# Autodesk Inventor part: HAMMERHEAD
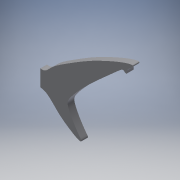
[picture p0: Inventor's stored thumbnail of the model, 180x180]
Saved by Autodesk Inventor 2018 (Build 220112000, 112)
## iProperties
Created: 2019-06
Part Number: HAMMERHEAD
Material: Generic
Document SubType Name: Modeling
Designer: multivac
Density: 1 g/cm^3
Appearance: Default
Author: multivac
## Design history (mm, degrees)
sketch "Sketch1"
  geometry: L1 (-121.659, 50.404)-(56.189, 50.404); L2 (56.189, 50.404)-(56.189, -28.23); L3 (56.189, -28.23)-(-121.659, -28.23); L4 (-121.659, -28.23)-(-121.659, 50.404); L5 (0.653, 15.594)-(3.508, 15.097); L6 (3.508, 15.097)-(6.301, 17.022); L7 (6.301, 17.022)-(9.219, 21.367); L8 (9.219, 21.367)-(18.033, 27.016); L9 (18.033, 27.016)-(25.42, 31.733); L10 (25.42, 31.733)-(37.711, 39.368); L11 (37.711, 39.368)-(50.622, 45.576); L12 (50.622, 45.576)-(62.913, 50.976); L13 (62.913, 50.976)-(70.61, 53.149); L14 (70.61, 53.149)-(71.26, 52.492); L15 (71.26, 52.492)-(71.26, 51.488); L16 (71.26, 51.488)-(66.753, 48.312); L17 (66.753, 48.312)-(66.613, 46.818); L18 (66.613, 46.818)-(66.847, 45.183); L19 (66.847, 45.183)-(66.076, 44.459); L20 (66.076, 44.459)-(64.722, 45.23); L21 (64.722, 45.23)-(63.858, 46.374); L22 (63.858, 46.374)-(62.223, 45.883); L23 (62.223, 45.883)-(53.746, 37.92); L24 (53.746, 37.92)-(35.368, 22.064); L25 (35.368, 22.064)-(23.061, 7.796); L26 (23.061, 7.796)-(20.586, 3.592); L27 (20.586, 3.592)-(22.36, -0.495); L28 (22.36, -0.495)-(24.999, -6.473); L29 (24.999, -6.473)-(30.417, -14.459); L30 (30.417, -14.459)-(32.379, -16.444); L31 (32.379, -16.444)-(31.748, -17.705); L32 (31.748, -17.705)-(28.409, -16.865); L33 (28.409, -16.865)-(19.161, -10.793); L34 (19.161, -10.793)-(14.701, -7.524); L35 (14.701, -7.524)-(8.396, -0.495); L36 (8.396, -0.495)-(4.402, 2.775); L37 (4.402, 2.775)-(0.653, 3.09); L38 (0.653, 15.594)-(0.653, 3.09); 1 other entity
  constraints: 2 end point, 2 vertical, 5 other
extrude "Extrusion1" new body sketch "Sketch1" distance "d16" = 5; taper "d17" = 0 deg
sketch "Sketch2"
  geometry: L1 (-0.653, 0)-(-0.653, 5) reference; L2 (-0.653, 5)-(-74.207, 2.5); L3 (-74.207, 2.5)-(-0.653, 0); L4 (-0.653, 0)-(-0.653, 5); 1 further point
  constraints: 6 end point, 1 collinear
extrude "Extrusion2" sketch "Sketch2" distance "d26" = 60; taper "d28" = 0 deg; dims "d27" = 25, "d29" = 0
sketch "Sketch3"
  geometry: L1 (0, 0)-(0, 12.504) reference; L2 (0, 6.252)-(0, 10.252); L3 (0, 10.252)-(5, 10.252); L4 (5, 12.504)-(5, 0) reference; L5 (5, 10.252)-(5, 2.252); L6 (5, 2.252)-(0, 2.252); L7 (0, 6.252)-(0, 2.252)
  constraints: 10 end point, 4 point on line, 1 collinear, 1 horizontal, 1 midpoint, 1 perpendicular
  dimensions: "d30" = 4 distance of L2.start L2.end; "d31" = 8 distance of L3.end L5.end
extrude "Extrusion3" join sketch "Sketch3" distance "d32" = 15; taper "d33" = 0 deg
fillet "Fillet1" dims "d34" = 3
sketch "Sketch4"
  geometry: L1 (0, 0)-(0, 8) reference; C1 r 2 at (3.75, 4); C2 r 2 at (11.25, 4); 1 further point
  constraints: 2 centre point
  dimensions: "d37" = 4 diameter of C1; "d38" = 4 diameter of C2
extrude "Extrusion4" cut sketch "Sketch4" distance "d39" = 15; taper "d40" = 0 deg
body "Solid1"
node "Image1"
